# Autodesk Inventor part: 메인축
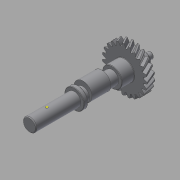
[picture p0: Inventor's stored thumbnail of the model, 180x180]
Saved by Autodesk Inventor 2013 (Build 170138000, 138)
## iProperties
Created: 2016-12
Part Number: 메인축
Material: 강철, 탄소
Document SubType Name: Modeling
Designer: mduedu
Categories: <?xml version="1.0" encoding="UTF-16"?> <MemberInstance><Categories><FamilyTemplate><FamilyTemplateParameter ValueType="xs:double" Id="1" ObjectReferenceKey="da
Density: 1 g/cm^3
CustomPartVersion: 1
Author: mduedu
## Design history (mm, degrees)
sketch "Sketch1"
  geometry: C1 r 28.558 at (0, 0)
  constraints: 1 centre point
  dimensions: "d0" = 57.11622 diameter of C1 (= da_da)
extrude "Extrusion1" new body sketch "Sketch1" distance "d1" = 10 (= da_b); taper "d2" = 0 deg
workplane "Work Plane2"
sketch "Sketch2"
  geometry: C1 r 28.558 at (0, 0) reference; C2 r 26.558 at (0, 0)
  constraints: 1 centre point, 1 coincident
  dimensions: "d3" = 53.11622 diameter of C2 (= da_dw)
feature "피치 지름" sketch "Sketch2" dims "d4" = 10, "d5" = 0
workplane "Work Plane8"
workplane "Work Plane9"
feature "스퍼 기어" dims "da_b" = 10, "da_d" = 53.11622, "da_aw" = 43.87862, "da_da" = 57.11622, "da_df" = 48.11622, "da_dw" = 53.11622, angle "da_beta" = 30 deg, "da_lefttooth" = 10, "da_righttooth" = 0
sketch "스케치3"
  geometry: C1 r 12.5 at (0, 0); 1 further point
  constraints: 1 centre point, 1 coincident
  dimensions: "d49" = 25 diameter of C1
extrude "돌출2" join sketch "스케치3" distance "d50" = 16; taper "d51" = 0 deg
sketch "스케치4"
  geometry: C1 r 8.5 at (0, 0); 1 further point
  constraints: 1 centre point, 1 coincident
  dimensions: "d52" = 17 diameter of C1
extrude "돌출3" join sketch "스케치4" distance "d53" = 105; taper "d54" = 0 deg
sketch "스케치5"
  geometry: C1 r 7.5 at (0, 0); 1 further point
  constraints: 1 centre point, 1 coincident
  dimensions: "d55" = 15 diameter of C1
extrude "돌출4" join sketch "스케치5" distance "d56" = 16; taper "d57" = 0 deg
sketch "스케치6"
  geometry: C1 r 4 at (0, 0); 1 further point
  constraints: 1 centre point, 1 coincident
  dimensions: "d58" = 8 diameter of C1
extrude "돌출5" join sketch "스케치6" distance "d59" = 7; taper "d60" = 0 deg
chamfer "모따기1" distance "d61" = 0.5; stored, may be unused: second distance "d62" = 2, angle "d63" = 45 deg
fillet "모깎기1" dims "d64" = 0.5
node "작업 평면11"
sketch "스케치7"
  geometry: C1 r 11.5 at (0, 3); C2 r 8.5 at (0, 0) reference; 1 further point
  constraints: 1 centre point, 1 tangent, 1 vertical alignment
  dimensions: "d66" = 3 distance of point (0, 0) C1.centre; "d67" = 23 diameter of C1 (derived)
extrude "돌출6" join sketch "스케치7" stored distance "d68" = 24; taper "d69" = 0 deg
node "작업 평면12"
sketch "스케치8"
  geometry: C1 r 12.5 at (0, 0) reference; 1 further point
extrude "돌출7" join sketch "스케치8" distance "d71" = 5; taper "d72" = 0 deg
chamfer "모따기2" distance "d73" = 0.5; stored, may be unused: second distance "d74" = 2, angle "d75" = 45 deg
chamfer "모따기3" distance "d76" = 1; stored, may be unused: second distance "d77" = 2, angle "d78" = 45 deg
node "작업 평면13"
sketch "스케치9" dims "d81" = 18
  geometry: L1 (2.5, 95.5)-(-2.5, 95.5); L2 (-2.5, 95.5)-(-2.5, 82.5); L3 (-2.5, 82.5)-(2.5, 82.5); L4 (2.5, 82.5)-(2.5, 95.5); L5 (-7.5, 105)-(7.5, 105) reference; 3 further points
  constraints: 8 end point, 2 horizontal alignment, 2 midpoint, 2 parallel, 1 horizontal, 1 perpendicular, 1 vertical alignment, 4 other
  dimensions: "d79" = 5 distance between parallel lines of L2 L4; "d82" = 7 dimension on L5
extrude "돌출8" cut sketch "스케치9" distance "d83" = 3; taper "d84" = 0 deg
sketch "스케치10"
  geometry: L1 (-8.5, 74)-(-8.5, 130) reference; L2 (8.5, 74)-(8.5, 130) reference; L3 (8.5, 109)-(-8.5, 109); L4 (-7.5, 131)-(7.5, 131) reference; L5 (8.5, 109)-(7, 109); L6 (7, 109)-(8.5, 107.5); L7 (8.5, 107.5)-(8.5, 109); 1 further point
  constraints: 8 end point, 4 point on line, 2 perpendicular
  dimensions: "d85" = 22 distance between parallel lines of L3 L4; "d86" = 45 deg angle of L6 L5; "d87" = 3 diameter of L6.end L3
revolve "회전1" stored, may be unused: angle "d88" = 90 deg
node "작업점1"
body "Solid1"
body "Srf1"
other parameters: "d16" = 43.87862 (= da_aw), "d17" = 0, "d34" = 1.36591 (computed from da_z), "d39" = 0, "d41" = 0, "d43" = 43.87862 (= da_aw), "d46" = 43.87862 (= da_aw), "d47" = 0, "d48" = 0, "d65" = 25, "d70" = 48
